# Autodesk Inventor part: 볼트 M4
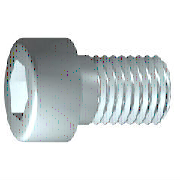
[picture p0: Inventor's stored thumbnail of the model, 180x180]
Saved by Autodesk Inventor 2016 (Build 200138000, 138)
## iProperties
IsCustomPart: 0
Created: 2016-04
Part Number: 볼트 M4
Material: 강철, 연강
Description: 6각머리 태핑 나사
Document SubType Name: Modeling
Standard: KS B 1003
Designer: mdu
Standards Organization: KS
Language: ko-KR
Size Designation: M 4 x 10
Categories: <MemberInstance><Categories><Category DisplayName="조임쇠" InternalName="e4da775c-781d-43d5-af7c-5136215cf5a6" Mnemonic="FSTN"><Category DisplayName="볼트" InternalN
Density: 7.86 g/cm^3
Mass: 2.0371 g
Surface Area: 3.0572 cm^2
Volume: 0.259174 cm^3
Appearance: 금속 1800F 열
Author: mdu
Revision Number: 1
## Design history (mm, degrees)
sketch "스케치1"
  geometry: L1 (-1, 0)-(10, 0); L2 (10, 0)-(10, 2); L3 (10, 2)-(1.75, 2); L4 (1.75, 2)-(1.32, 2); L5 (1.32, 2)-(0, 2); L6 (0, 2)-(0, 3.5); L7 (0, 3.5)-(-4, 3.5); L8 (-4, 3.5)-(-4, 1.732); L9 (-4, 1.732)-(-2, 1.732); L10 (-2, 1.732)-(-1, 0); L11 (-6.8, 0)-(12.8, 0) reference; L12 (0, -0.7)-(0, 4.2) reference; L13 (1.75, 2)-(0, 2)
  constraints: 22 end point, 6 parallel, 2 collinear, 2 perpendicular, 1 horizontal, 1 point on line
  dimensions: "d1" = 8.25 distance from line of L3.end L2 (= GEL); "d2" = 0.42952 distance of L4.end L3.end (computed from GAL); "d3" = 4 distance between parallel lines of L8 L6 (= KOH); "d4" = 2 distance of L8.end L9.end (= INTI); "d5" = 60 deg angle of L10 L1; "d6" = 4 diameter of L3 L1 (= GD); "d7" = 4 diameter of L5 L1 (= BDM); "d8" = 3.4641 diameter of L9 L1 (= 1.1547 x SW); "d9" = 7 diameter of L7 L1 (= KOD); "d26" = 10 distance between parallel lines of L12 L2 (= NLG)
revolve "본체" sketch "스케치1" stored, may be unused: angle "d10" = 90 deg
sketch "스케치2"
  geometry: L1 (0, -4.9)-(0, 4.9) reference; L2 (-4.9, 0)-(4.9, 0) reference; L3 (1.732, 0)-(0.866, -1.5); L4 (0.866, -1.5)-(-0.866, -1.5); L5 (-0.866, -1.5)-(-1.732, 0); L6 (-1.732, 0)-(-0.866, 1.5); L7 (-0.866, 1.5)-(0.866, 1.5); L8 (0.866, 1.5)-(1.732, 0); 2 further points
  constraints: 12 end point, 1 coincident, 1 horizontal alignment, 1 point on line, 12 other
extrude "슬롯" join sketch "스케치2" stored distance "d11" = 10; taper "d12" = 0 deg
workplane "Work Plane1"
fillet "Fillet2" dims "d30" = 0.1 (= R)
body "Solid1"
fillet "모깎기1" dims "d17" = 0.4 (= RR)
feature "스레드" dims "d13" = 8.25 (= GEL), "d14" = 0
chamfer "모따기1" distance "d15" = 0.42941 (= -0.5 x SPD + 0.5 x GD); stored, may be unused: second distance "d16" = 0.42941 (= GUL), angle "d27" = 45 deg
other parameters: "GD" = 4 (= NND) [user parameter; used in 2 equation terms], "NLG" = 10 [user parameter; used in 1 equation term], "GEL" = 8.25 [user parameter; used in 2 equation terms], "KOD" = 7 [user parameter; used in 1 equation term], "KOH" = 4 [user parameter; used in 1 equation term], "INTI" = 2 [user parameter; used in 1 equation term], "GAL" = 0.42941 (= 0.61345 x PTC) [user parameter; used in 1 equation term], "GUL" = 0.42941 (= 0.61345 x PTC) [user parameter; used in 1 equation term], "BDM" = 4 (= NND) [user parameter; used in 1 equation term], "SW" = 3 [user parameter; used in 2 equation terms], "RR" = 0.4 [user parameter; used in 1 equation term], "SPD" = 3.14117 (= NND - 1.2269 x PTC) [user parameter; used in 1 equation term], "d19" = 0, "d28" = 0, "d29" = 0, "R" = 0.1 [user parameter; used in 1 equation term], "PHH" = 0.2 [user parameter], "GD1" = 3.14117 (= THREADDIA - 1.2269 x PTC) [user parameter], "THREADDIA" = 4 [user parameter; used in 1 equation term], "FAWI" = 45 deg [user parameter], "TPU" = 14.28571 (computed from PTC) [user parameter], "PTC" = 0.7 [user parameter; used in 5 equation terms], "NND" = 4 [user parameter; used in 3 equation terms], "TOA" = 30 deg [user parameter], "E0" = 3.465 (= 1.155 x SW) [user parameter]
